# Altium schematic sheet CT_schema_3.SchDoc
size 205 x 174 mm
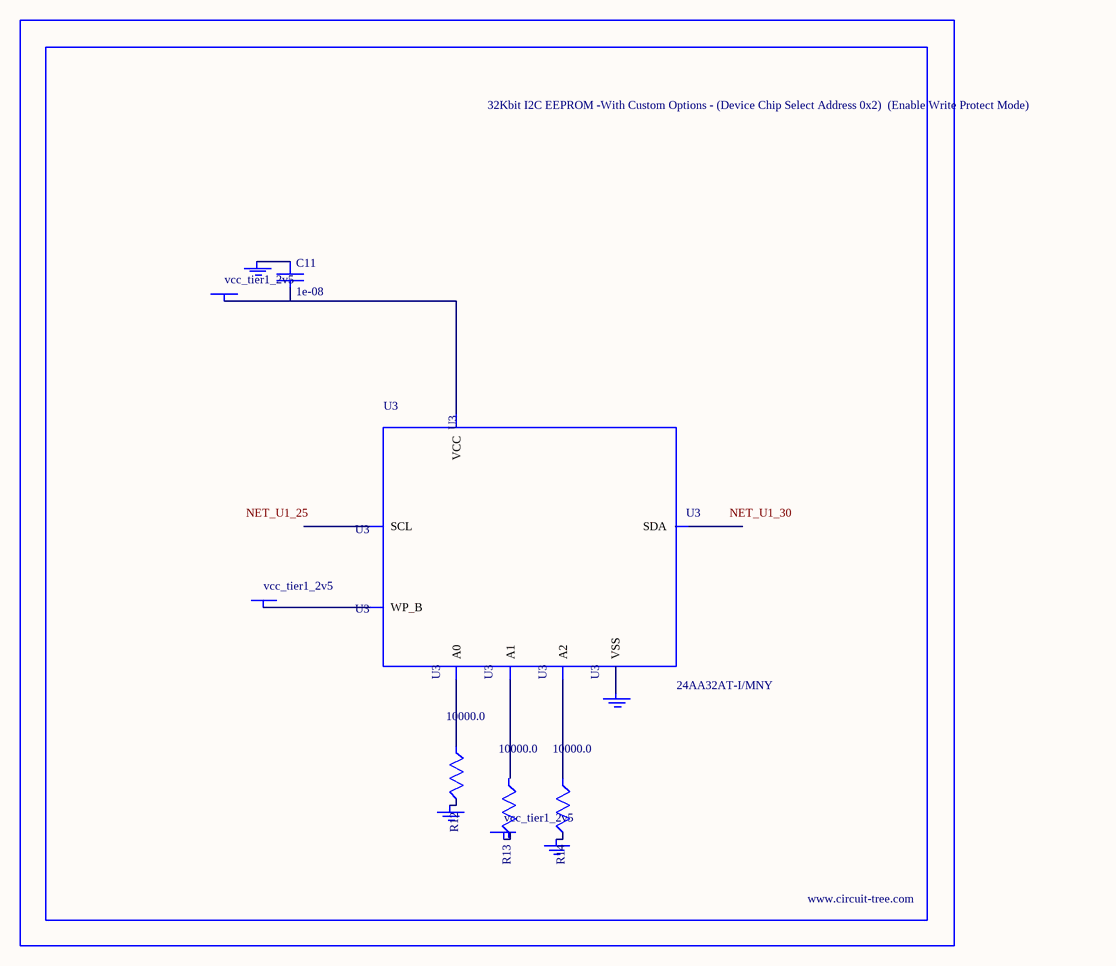
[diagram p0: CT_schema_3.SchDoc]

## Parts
BORDER2  (no value)
C11  1e-08  [C0402]
GND_INSTANCE_2_0  (no value)
GND_INSTANCE_2_1  (no value)
GND_INSTANCE_2_2  (no value)
GND_INSTANCE_2_3  (no value)
POWER_INSTANCE_2_0  vcc_tier1_2v5
POWER_INSTANCE_2_1  vcc_tier1_2v5
POWER_INSTANCE_2_2  vcc_tier1_2v5
R12  10000.0  [R0603]
R13  10000.0  [R0603]
R14  10000.0  [R0603]
U3  24AA32AT-I/MNY  [TDFN-8/6MM]

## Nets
NetC11_1: C11.1 GND_INSTANCE_2_2.0(GND)
NetC11_2: C11.2 POWER_INSTANCE_2_2.0(PWR) U3.8(VCC)
NetGND_INSTANCE_2_0_0: GND_INSTANCE_2_0.0(GND) R12.2
NetGND_INSTANCE_2_1_0: GND_INSTANCE_2_1.0(GND) R14.2
NetGND_INSTANCE_2_3_0: GND_INSTANCE_2_3.0(GND) U3.4(VSS)
NetPOWER_INSTANCE_2_1_0: POWER_INSTANCE_2_1.0(PWR) U3.7(WP_B)
NetR12_1: R12.1 U3.1(A0)
NetR14_1: R14.1 U3.3(A2)

Not connected (* = marked no-connect by the designer): POWER_INSTANCE_2_0 0(PWR); R13 1 2; U3 2(A1) 5(SDA) 6(SCL)

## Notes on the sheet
- Labels drawn without touching a wire or pin: NET_U1_25, NET_U1_30

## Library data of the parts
BORDER2 = BORDER_PAGE2
C11 = C0402C103K3RAC
GND_INSTANCE_2_0-GND_INSTANCE_2_3 = GND
POWER_INSTANCE_2_0-POWER_INSTANCE_2_2 = PWR
R12-R14 = RC0603JR-0710KL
